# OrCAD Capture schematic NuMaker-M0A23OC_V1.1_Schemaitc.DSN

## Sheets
1 Nu-Link2-Me: size A3; title: Nu-Link2-Me; rev: 1.0; company: CMHuang; note: Nu-Link2-Me
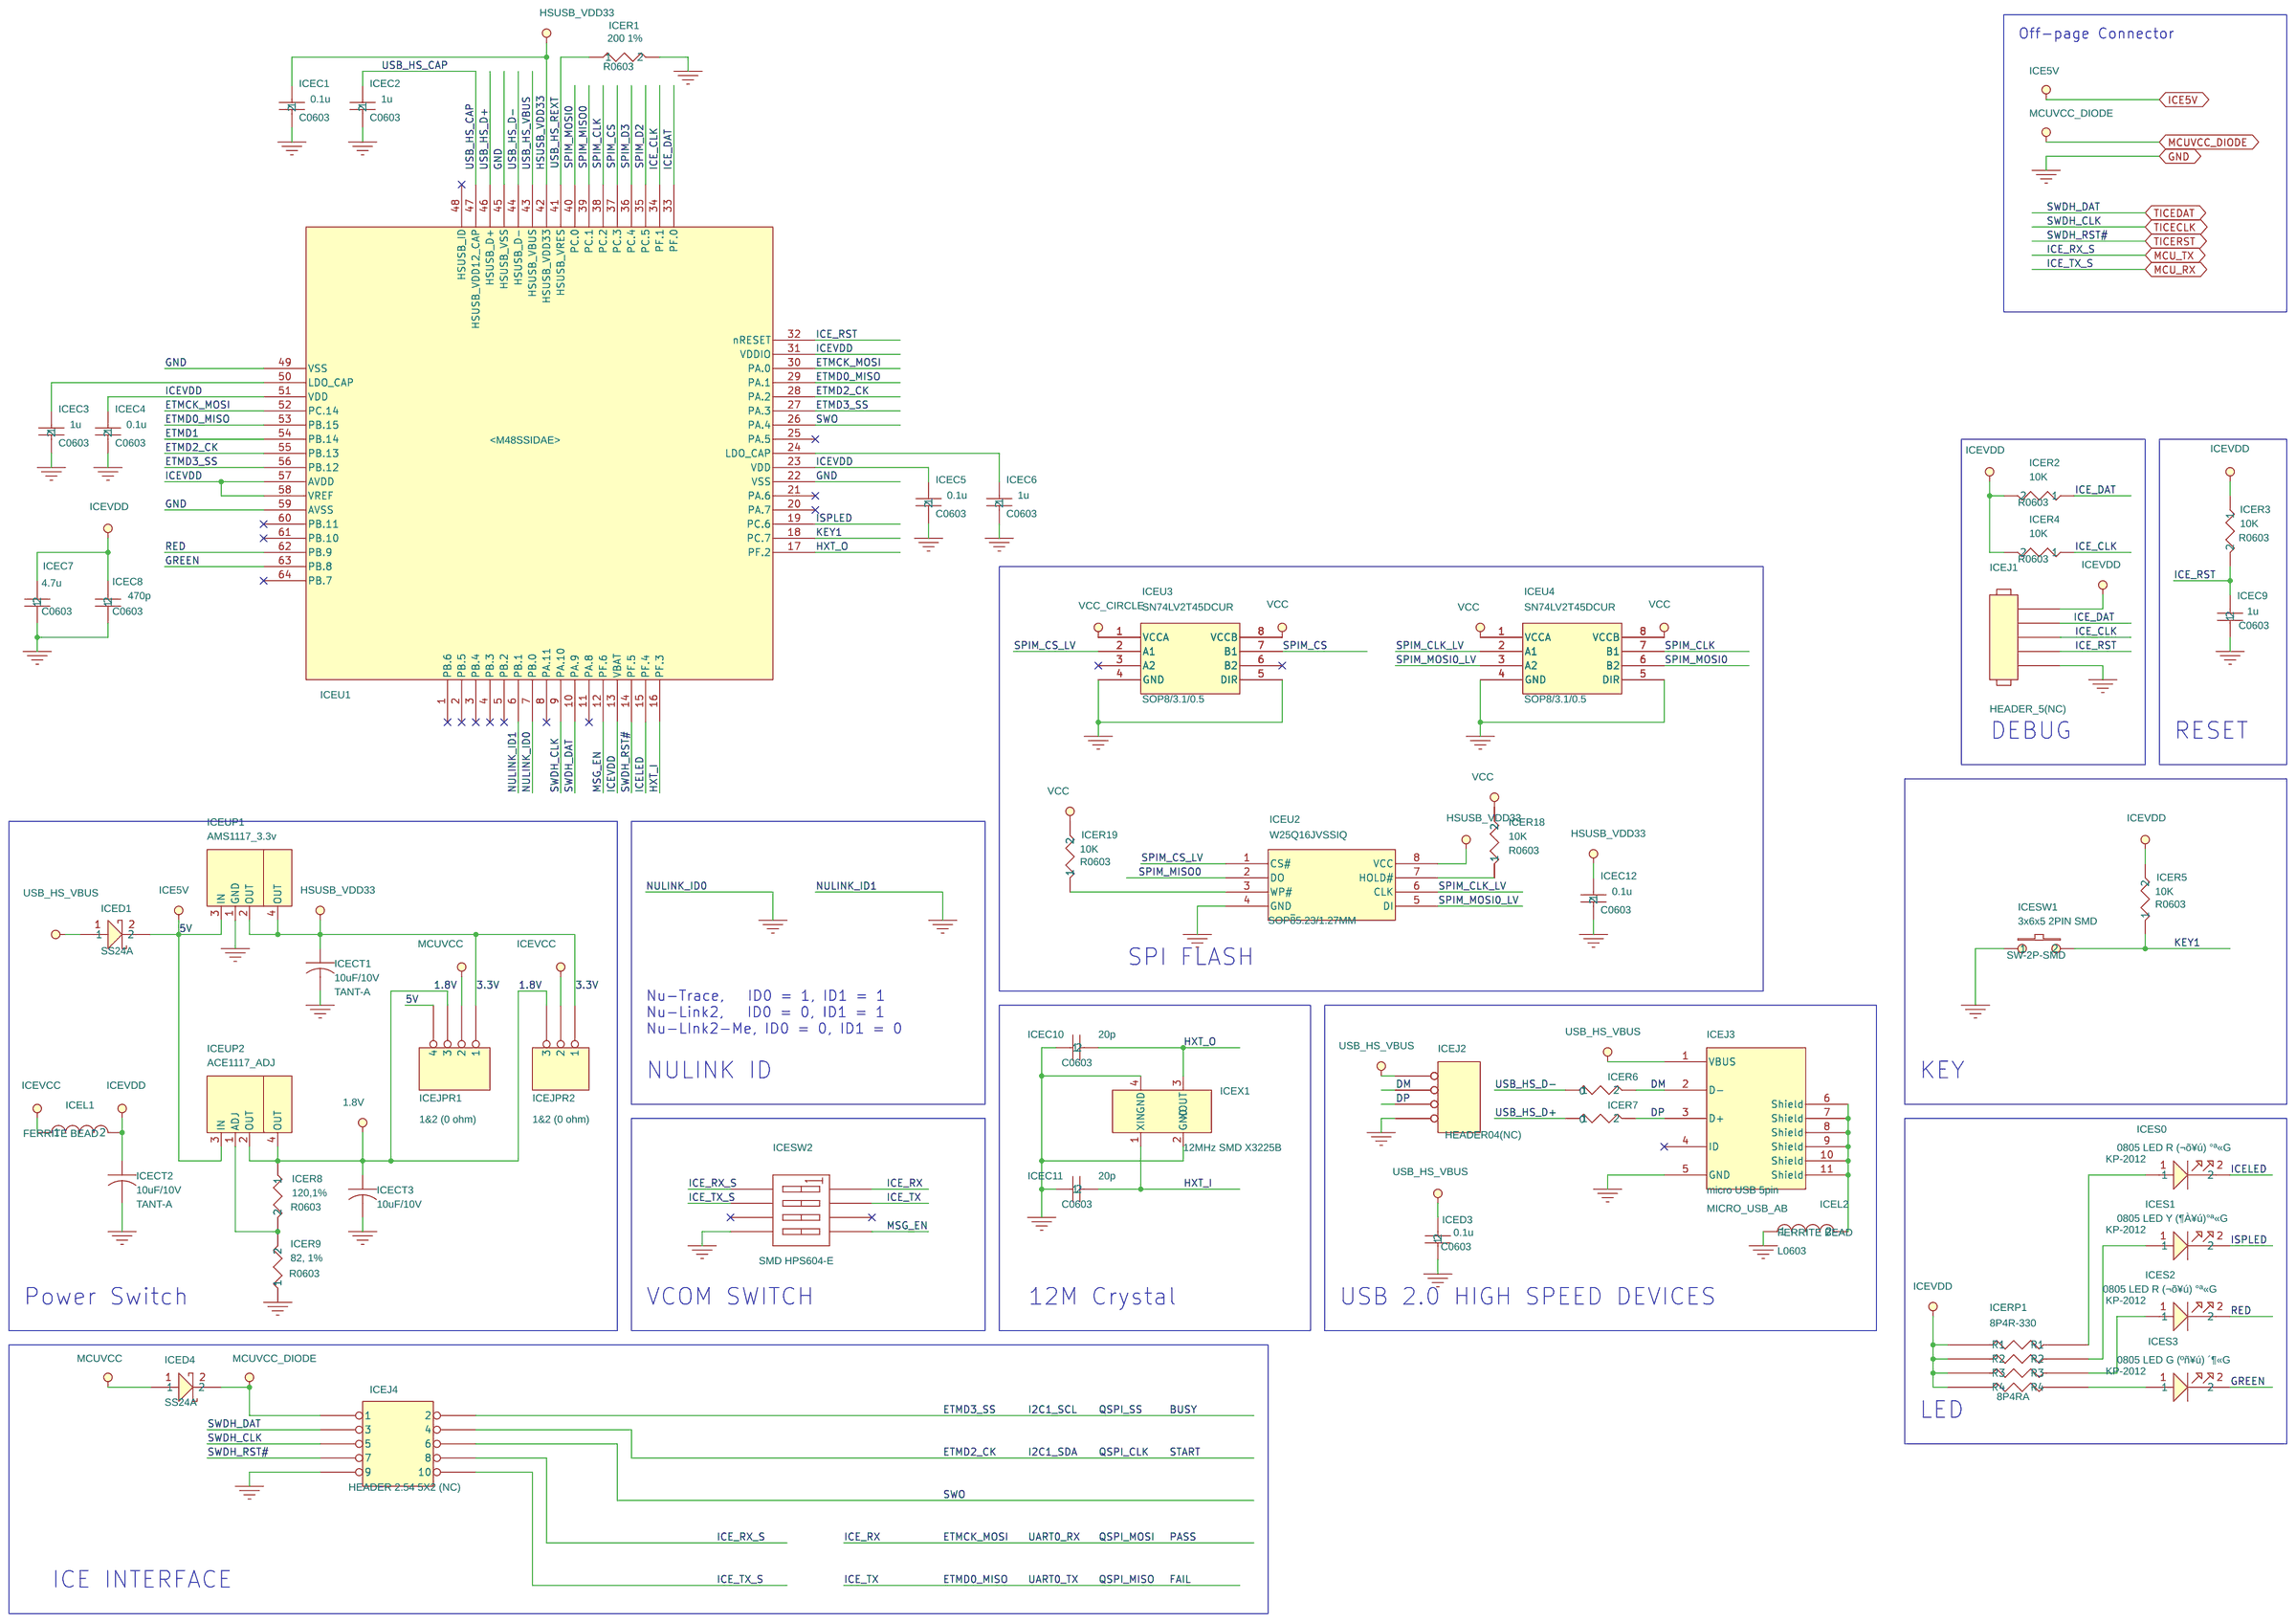
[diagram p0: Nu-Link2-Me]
2 M0A23OC1AC: size Custom; title: M0A23OC1AC; rev: v1.1; note: NuMaker-M0A23OC
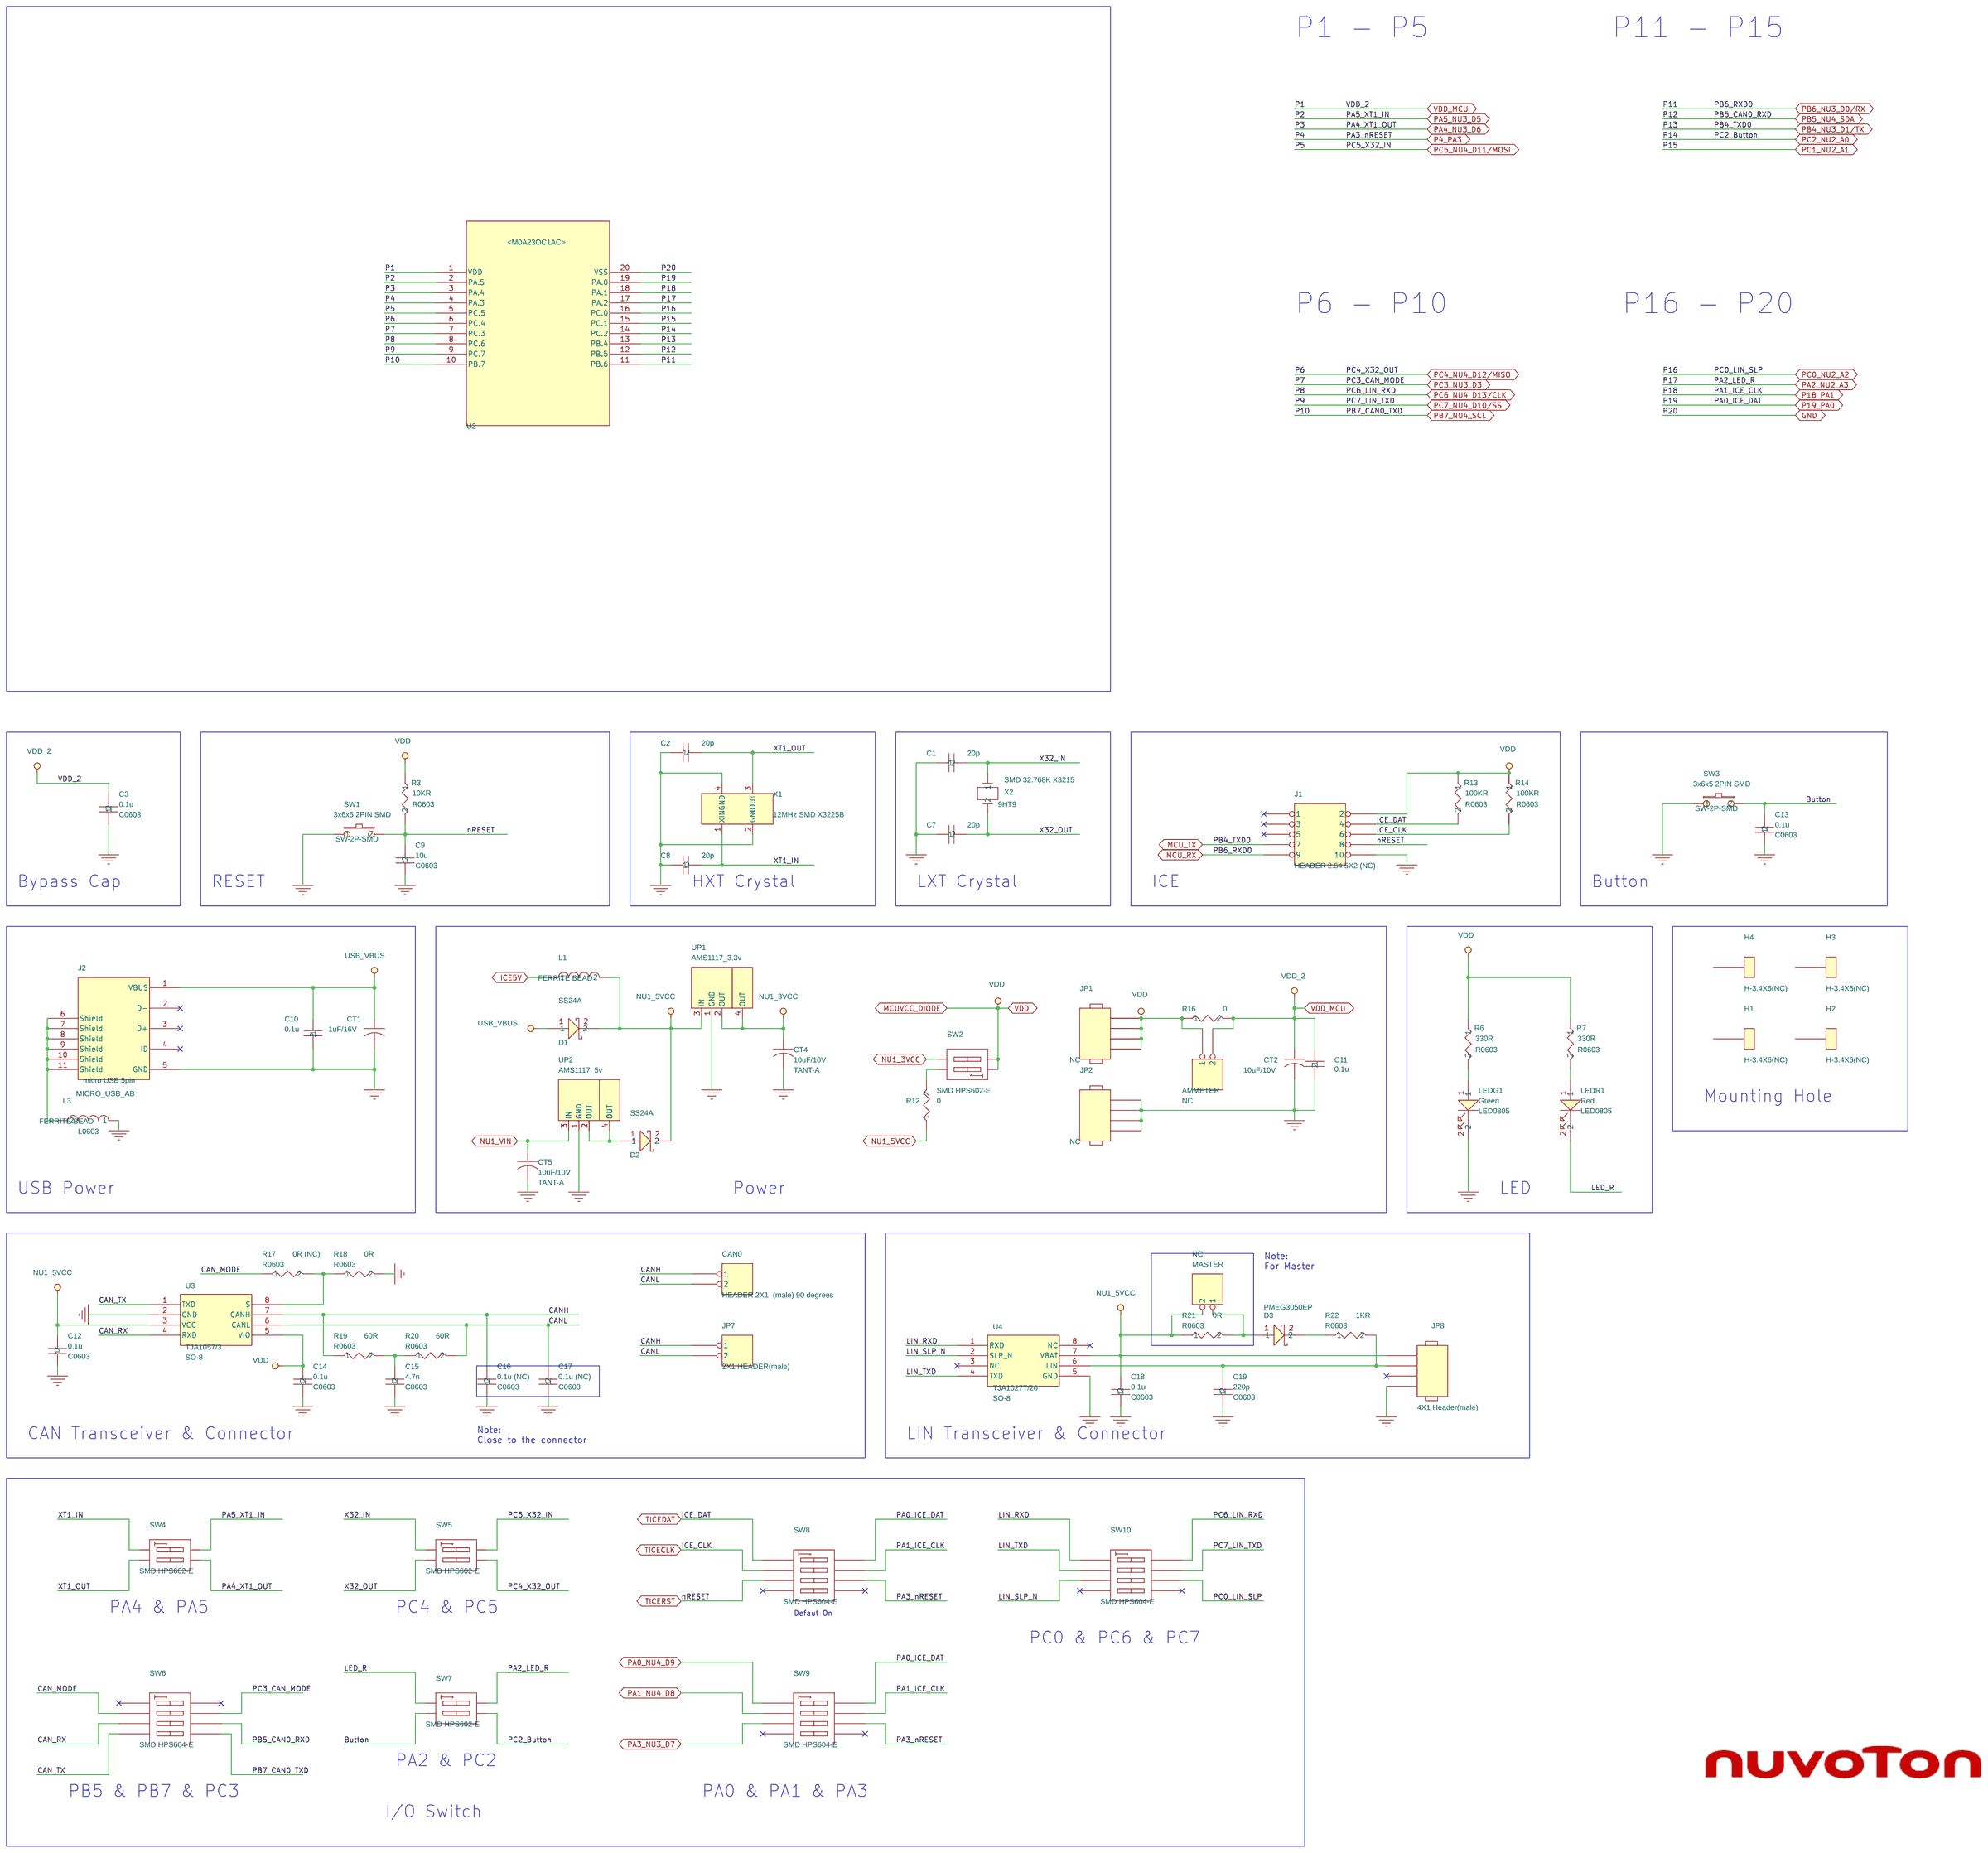
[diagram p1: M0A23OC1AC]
3 Ext. Connector: size Custom; title: Ext. Connector; rev: v1.1; note: NuMaker-M0A23OC
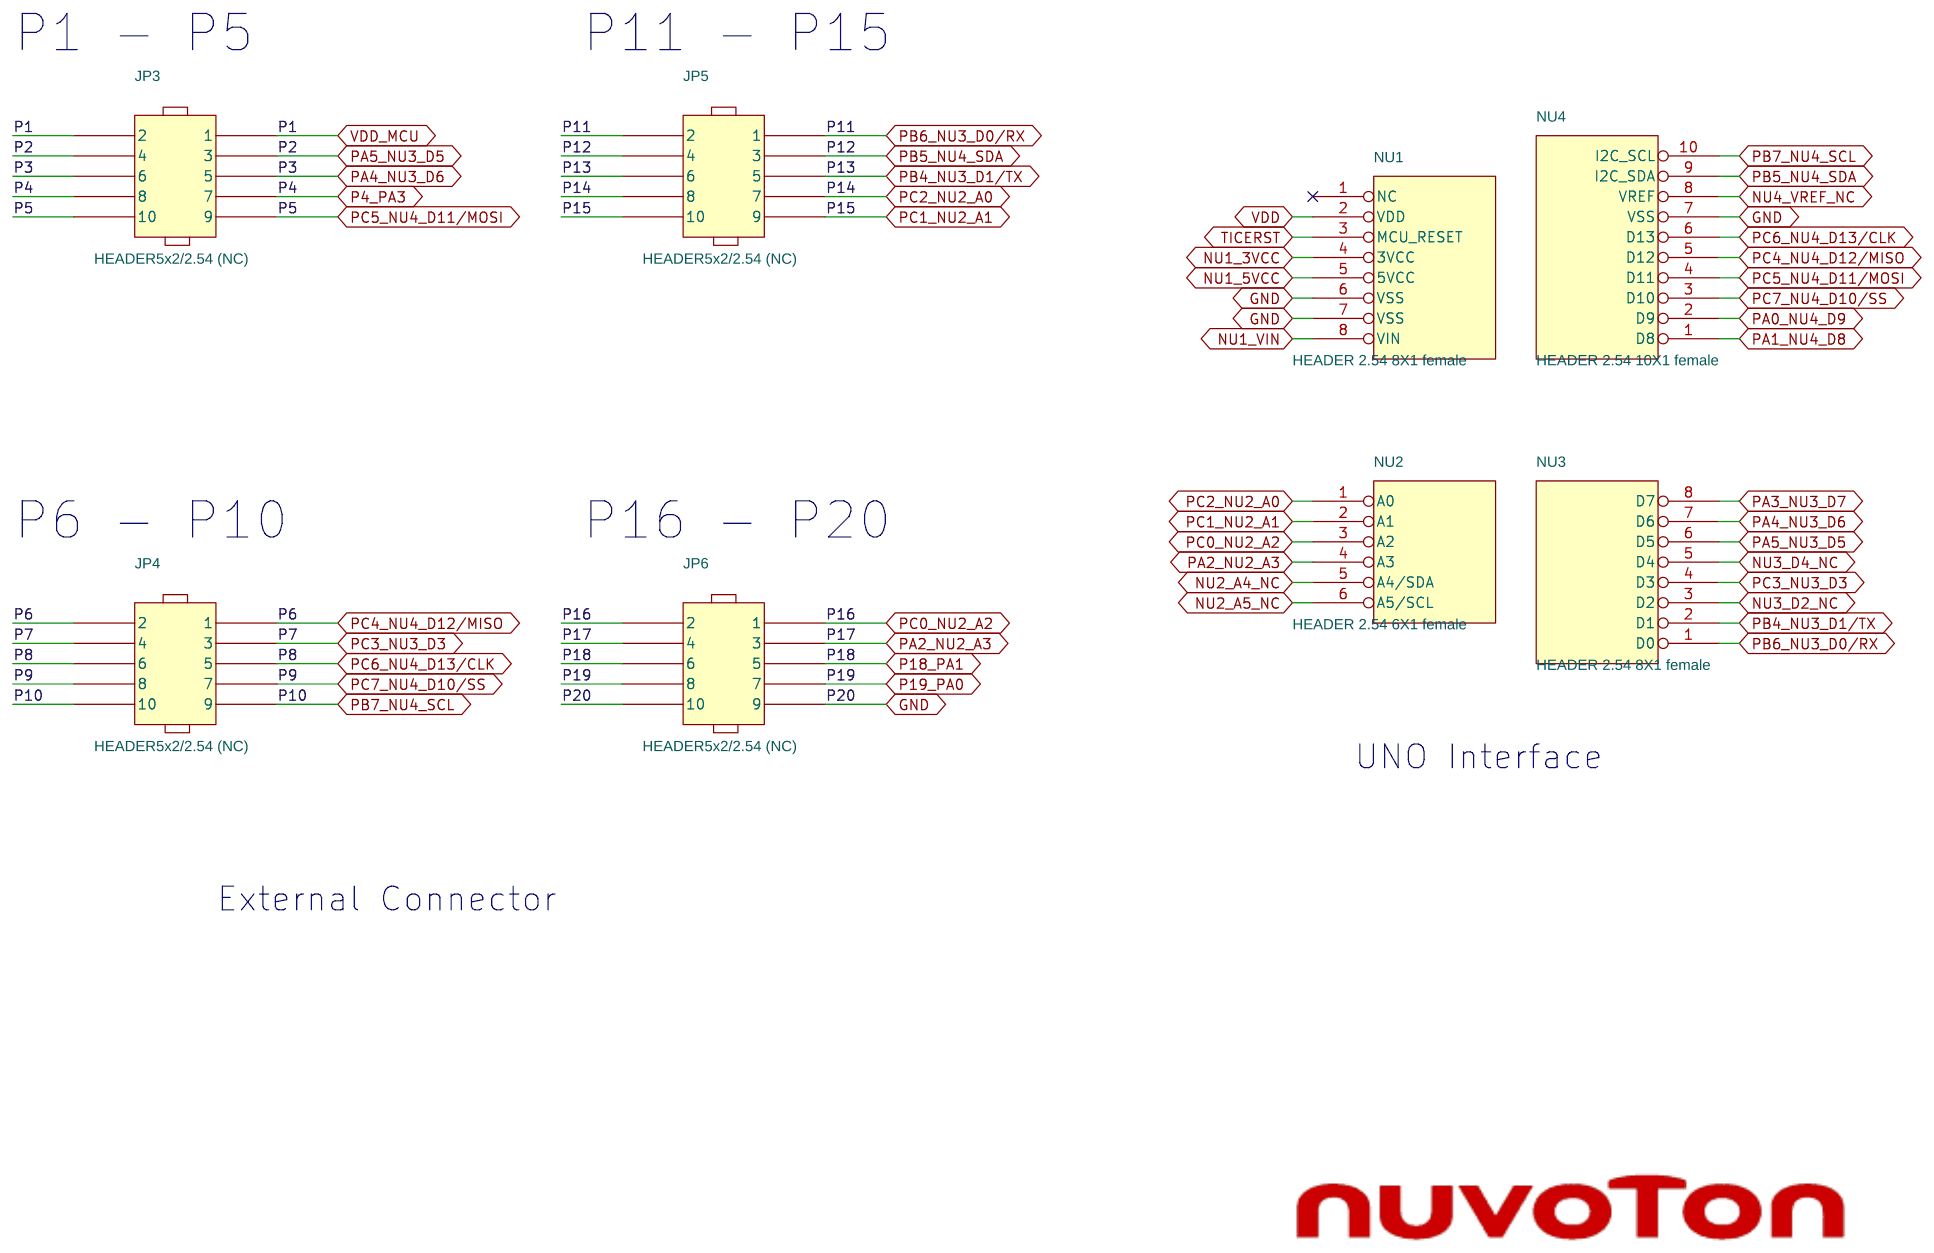
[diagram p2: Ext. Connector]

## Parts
sheet Ext. Connector
JP3  HEADER5x2/2.54 (NC)  [HEADER5x2/2.54]
JP4  HEADER5x2/2.54 (NC)  [HEADER5x2/2.54]
JP5  HEADER5x2/2.54 (NC)  [HEADER5x2/2.54]
JP6  HEADER5x2/2.54 (NC)  [HEADER5x2/2.54]
NU1  HEADER 2.54 8X1 female  [SIP-8P]
NU2  HEADER 2.54 6X1 female  [SIP-6P]
NU3  HEADER 2.54 8X1 female  [SIP-8P]
NU4  HEADER 2.54 10X1 female  [SIP-10P]
sheet M0A23OC1AC
AMMETER  NC  [HEADER2X1]
C1  20p  [C0603]
C2  20p  [C0603]
C3  0.1u  [C0603]
C7  20p  [C0603]
C8  20p  [C0603]
C9  10u  [C0603]
C10  0.1u  [C0603]
C11  0.1u  [C0603]
C12  0.1u  [C0603]
C13  0.1u  [C0603]
C14  0.1u  [C0603]
C15  4.7n  [C0603]
C16  0.1u (NC)  [C0603]
C17  0.1u (NC)  [C0603]
C18  0.1u  [C0603]
C19  220p  [C0603]
CAN0  HEADER 2X1  (male) 90 degrees  [SIP/2P_3.5MM]
CT1  1uF/16V  [TANT-A]
CT2  10uF/10V  [TANT-A]
CT4  10uF/10V  [TANT-A]
CT5  10uF/10V  [TANT-A]
D1  SS24A  [RB060L]
D2  SS24A  [RB060L]
D3  PMEG3050EP  [SOD-123-A(B)]
H1  H-3.4X6(NC)  [H-3.4X6]
H2  H-3.4X6(NC)  [H-3.4X6]
H3  H-3.4X6(NC)  [H-3.4X6]
H4  H-3.4X6(NC)  [H-3.4X6]
J1  HEADER 2.54 5X2 (NC)  [HEADER5X2]
J2  micro USB 5pin  [MICRO_USB_AB]
JP1  NC  [header1x4]
JP2  NC  [header1x4]
JP7  2X1 HEADER(male)  [HEADER2X1]
JP8  4X1 Header(male)  [header1x4]
L1  FERRITE BEAD  [L0603]
L3  FERRITE BEAD  [L0603]
LEDG1  Green  [LED0805]
LEDR1  Red  [LED0805]
MASTER  NC  [HEADER2X1]
R3  10KR  [R0603]
R6  330R  [R0603]
R7  330R  [R0603]
R12  0  [R0603]
R13  100KR  [R0603]
R14  100KR  [R0603]
R16  0  [R0603]
R17  0R (NC)  [R0603]
R18  0R  [R0603]
R19  60R  [R0603]
R20  60R  [R0603]
R21  0R  [R0603]
R22  1KR  [R0603]
SW1  3x6x5 2PIN SMD  [SW-2P-SMD]
SW2  SMD HPS602-E  [SW1X2]
SW3  3x6x5 2PIN SMD  [SW-2P-SMD]
SW4  SMD HPS602-E  [SW1X2]
SW5  SMD HPS602-E  [SW1X2]
SW6  SMD HPS604-E  [SW1X4]
SW7  SMD HPS602-E  [SW1X2]
SW8  SMD HPS604-E  [SW1X4]
SW9  SMD HPS604-E  [SW1X4]
SW10  SMD HPS604-E  [SW1X4]
U2  M0A23OC1AC  [MCU_SSOP20_7.8X7.2mm]
U3  TJA1057/3  [SO-8]
U4  TJA1027T/20  [SO-8]
UP1  AMS1117_3.3v  [SOT-223-1]
UP2  AMS1117_5v  [SOT-223-1]
X1  12MHz SMD X3225B  [CRYSTAL_SMD]
X2  SMD 32.768K X3215  [9HT9]
sheet Nu-Link2-Me
ICEC1  0.1u  [C0603]
ICEC2  1u  [C0603]
ICEC3  1u  [C0603]
ICEC4  0.1u  [C0603]
ICEC5  0.1u  [C0603]
ICEC6  1u  [C0603]
ICEC7  4.7u  [C0603]
ICEC8  470p  [C0603]
ICEC9  1u  [C0603]
ICEC10  20p  [C0603]
ICEC11  20p  [C0603]
ICEC12  0.1u  [C0603]
ICECT1  10uF/10V  [TANT-A]
ICECT2  10uF/10V  [TANT-A]
ICECT3  10uF/10V  [TANT-A]
ICED1  SS24A  [RB060L]
ICED3  0.1u  [C0603]
ICED4  SS24A  [RB060L]
ICEJ1  HEADER_5(NC)  [HEADER5X1]
ICEJ2  HEADER04(NC)  [HEADER04]
ICEJ3  micro USB 5pin  [MICRO_USB_AB]
ICEJ4  HEADER 2.54 5X2 (NC)  [HEADER5X2]
ICEJPR1  1&2 (0 ohm)  [R0603X3]
ICEJPR2  1&2 (0 ohm)  [R0603X2]
ICEL1  FERRITE BEAD  [L0603]
ICEL2  FERRITE BEAD  [L0603]
ICER1  200 1%  [R0603]
ICER2  10K  [R0603]
ICER3  10K  [R0603]
ICER4  10K  [R0603]
ICER5  10K  [R0603]
ICER6  0  [R0603]
ICER7  0  [R0603]
ICER8  120,1%  [R0603]
ICER9  82, 1%  [R0603]
ICER18  10K  [R0603]
ICER19  10K  [R0603]
ICERP1  8P4R-330  [8P4RA]
ICES0  0805 LED R (¬õ¥ú) °ª«G  [KP-2012]
ICES1  0805 LED Y (¶À¥ú)°ª«G  [KP-2012]
ICES2  0805 LED R (¬õ¥ú) °ª«G  [KP-2012]
ICES3  0805 LED G (ºñ¥ú) ´¶«G  [KP-2012]
ICESW1  3x6x5 2PIN SMD  [SW-2P-SMD]
ICESW2  SMD HPS604-E  [SW1X4]
ICEU1  M48SSIDAE  [LQFP64_7x7_M48SSIDAE]
ICEU2  W25Q16JVSSIQ  [SOP8\5.23/1.27MM]
ICEU3  SN74LV2T45DCUR  [SOP8/3.1/0.5]
ICEU4  SN74LV2T45DCUR  [SOP8/3.1/0.5]
ICEUP1  AMS1117_3.3v  [SOT-223-1]
ICEUP2  ACE1117_ADJ  [SOT-223-1]
ICEX1  12MHz SMD X3225B  [CRYSTAL_SMD]

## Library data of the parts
JP3 = HEADER_5X2
JP4 = HEADER_5X2_3
JP5 = HEADER_5X2_2
JP6 = HEADER_5X2_1
NU1 = POWER_CONNECT_0
NU2 = ADC_CONNECT_0
NU3 = PWM0_CONNECT_0
NU4 = PWM1_CONNECT_1
AMMETER = HEADER_2_1
C1 = C_20p_3
C2 = C_20p_1
C3 = CAP-C_6: Package: 0603; element_no: C0004
C7 = C_20p_2
C8 = C_20p
C9 = CAP-C_8: Package: 0603; element_no: C0006
C10 = C_0.1u_1: element_no: C0004
C11 = C_0.1u: element_no: C0004
C12 ICEC2 = CAP-C_9: Package: 0603; element_no: C0006
C13 ICEC3 = CAP-C_2: Package: 0603; element_no: C0006
C14 = CAP-C_3: Package: 0603; element_no: C0006
C15 = CAP-C_5: Package: 0603; element_no: C0006
C16 = CAP-C: Package: 0603; element_no: C0006
C17 ICEC9 = CAP-C_7: Package: 0603; element_no: C0006
C18 = CAP-C_4: Package: 0603; element_no: C0006
C19 = CAP-C_1: Package: 0603; element_no: C0006
CAN0 = HEADER_2_2
CT1 = C_1uF_16V
CT2 CT4 CT5 ICECT1-ICECT3 = C_10uF_10V
D1 = D_SS24A_2
D2 ICED1 = D_SS24A_1
D3 ICED4 = D_SS24A
H1-H4 = TEST_POINT
ICEJ4 J1 = HEADER_5X2_v2
ICEJ3 J2 = micro_USB_5pin_0
JP1 JP2 JP8 = HEADER_4_v2
JP7 = HEADER_2
ICEL1 L1 = FERRITE_BEAD
ICEL2 L3 = FERRITE_BEAD_1
LEDG1 = LED_0_1: Package: KP-2012; Vendor: Kingbright
LEDR1 = LED_0: Package: KP-2012; Vendor: Kingbright
MASTER = HEADER_2_0
ICER3 R3 = R_0_4: Package: 0603
R6 = R_0_9: Package: 0603
ICER2 R7 = R_0_1: Package: 0603
R12 = R_0_2
ICER5 R13 = R_0_8: Package: 0603
R14 = R_0_10: Package: 0603
R16 = R_0_12
R17 = R_0_11: Package: 0603
ICER19 R18 = R_0_7: Package: 0603
ICER1 R19 = R_0_5: Package: 0603
ICER18 R20 = R_0_6: Package: 0603
ICER8 R21 = R_0: Package: 0603
ICER4 R22 = R_0_3: Package: 0603
SW1 = SW_PUSHBUTTON_0_1
SW2 SW4 SW5 SW7 = SW_DIP-4_2
ICESW1 SW3 = SW_PUSHBUTTON_0
ICESW2 SW6 SW8-SW10 = SW_DIP-4_SM
U2 = M0A23OC1AC_0: M023XC1AC: <M0A23OC1AC>
U3 = TJA1057_3
U4 = TJA1027T_20
ICEUP1 UP1 UP2 = TO-247_Regulator_10
ICEX1 X1 = Crystal_SMD_1
X2 = Xtal_32.768K
ICEC1 = CAP-C_11: Package: 0603; element_no: C0004
ICEC4 = CAP-C_10: Package: 0603; element_no: C0004
ICEC5 = CAP-C: Package: 0603; element_no: C0004
ICEC6 = CAP-C_12: Package: 0603; element_no: C0006
ICEC7 = CAP-C_5: Package: 0603
ICEC8 = CAP-C_6: Package: 0603
ICEC10 = CAP-C_3: Package: 0603
ICEC11 = CAP-C_4: Package: 0603
ICEC12 = CAP-C_8: Package: 0603; element_no: C0004
ICED3 = CAP-C_1: Package: 0603; element_no: C0004
ICEJ1 = HEADER_5
ICEJ2 = HEADER_4
ICEJPR1 = HEADER_3_0
ICEJPR2 = HEADER_3
ICER6 = R_33
ICER7 = R_33_1
ICER9 = R_0_2: Package: 0603
ICERP1 = R-PACK8_0
ICES0 = LED_0_3: Vendor: Kingbright
ICES1 = LED_0_2: Vendor: Kingbright
ICES2 = LED_0_1: Vendor: Kingbright
ICES3 = LED_0: Vendor: Kingbright
ICEU1 = M487SIDAE_0: M487SIDAE: <M48SSIDAE>
ICEU2 = W25P10_20_40_SOIC_0: Package: SOP8; Vendor: WINBOND
ICEU3 ICEU4 = SN74LV2T45
ICEUP2 = TO-247_Regulator_0

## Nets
1.8V: ICECT3.1 ICEJPR1.3 ICEJPR2.3 ICER8.1 ICEUP2.2(OUT) ICEUP2.4(OUT)
3.3V: ICEC1.1 ICEC12.1 ICECT1.1 ICEJPR1.1 ICEJPR2.1 ICER18.2 ICER19.2 ICEU1.42(HSUSB_VDD33) ICEU2.8(VCC) ICEU3.1(VCCA) ICEU4.1(VCCA) ICEUP1.2(OUT) ICEUP1.4(OUT)
GND: C1.1 C2.1 C3.1 C7.1 C8.1 C9.1 C10.2 C11.2 C12.1 C13.1 C14.1 C15.1 C16.1 C17.1 C18.1 C19.1 CT1.2 CT2.2 CT4.2 CT5.2 ICEC1.2 ICEC2.2 ICEC3.2 ICEC4.2 ICEC5.2 ICEC6.2 ICEC7.1 ICEC8.1 ICEC9.1 ICEC10.1 ICEC11.1 ICEC12.2 ICECT1.2 ICECT2.2 ICECT3.2 ICED3.1 ICEJ1.5 ICEJ2.4 ICEJ3.5(GND) ICEJ4.9 ICEL2.1 ICER1.2 ICER9.1 ICESW1.1 ICESW2.4(A4) ICEU1.6(PB.1) ICEU1.7(PB.0) ICEU1.22(VSS) ICEU1.45(HSUSB_VSS) ICEU1.49(VSS) ICEU1.59(AVSS) ICEU2.4(GND) ICEU3.4(GND) ICEU3.5(DIR) ICEU4.4(GND) ICEU4.5(DIR) ICEUP1.1(GND) ICEX1.2(GND) ICEX1.4(GND) J1.10 J2.5(GND) JP2.1 JP2.2 JP2.3 JP2.4 JP6.9 JP6.10 JP8.4 L3.1 LEDG1.2 NU1.6(VSS) NU1.7(VSS) NU4.7(VSS) R18.2 SW1.1 SW3.1 U2.20(VSS) U3.2(GND) U4.5(GND) UP1.1(GND) UP2.1(GND) X1.2(GND) X1.4(GND)
VDD: AMMETER.1 C14.2 ICED4.2 ICEJ4.1 J1.2 JP1.1 JP1.2 JP1.3 JP1.4 NU1.2(VDD) R3.1 R6.1 R7.1 R13.1 R14.1 R16.1 SW2.3(B1) SW2.4(B2) U3.5(VIO)
VDD_MCU: AMMETER.2 C3.2 C11.1 CT2.1 JP3.1 JP3.2 R16.2 U2.1(VDD)
BUSY: ICEJ4.2 ICEU1.27(PA.3) ICEU1.56(PB.12)
Button: C13.2 SW3.2 SW7.3(B1)
CAN_MODE: R17.1 SW6.7(B2)
CAN_RX: SW6.6(B3) U3.4(RXD)
CAN_TX: SW6.5(B4) U3.1(TXD)
CANH: C16.2 CAN0.1 JP7.1 R19.1 U3.7(CANH)
CANL: C17.2 CAN0.2 JP7.2 R20.2 U3.6(CANL)
DM: ICEJ2.2 ICEJ3.2(D-) ICER6.2
DP: ICEJ2.3 ICEJ3.3(D+) ICER7.2
ETMD1: ICEU1.54(PB.14)
ETMD2_CK: ICEJ4.4 ICEU1.28(PA.2) ICEU1.55(PB.13)
GREEN: ICES3.2 ICEU1.63(PB.8)
HXT_I: ICEC11.2 ICEU1.16(PF.3) ICEX1.1(XIN)
HXT_O: ICEC10.2 ICEU1.17(PF.2) ICEX1.3(XOUT)
ICE5V: ICED1.2 ICEJPR1.4 ICEUP1.3(IN) ICEUP2.3(IN) L1.1
ICE_CLK: ICEJ1.3 ICER4.1 ICEU1.34(PF.1)
ICE_DAT: ICEJ1.2 ICER2.1 ICEU1.33(PF.0)
ICE_RST: ICEC9.2 ICEJ1.4 ICER3.2 ICEU1.32(nRESET)
ICE_RX: ICESW2.8(B1) ICEU1.30(PA.0) ICEU1.52(PC.14)
ICE_TX: ICESW2.7(B2) ICEU1.29(PA.1) ICEU1.53(PB.15)
ICELED: ICES0.2 ICEU1.15(PF.4)
ICEVCC: ICEJPR2.2 ICEL1.1
ICEVDD: ICEC4.1 ICEC5.1 ICEC7.2 ICEC8.2 ICECT2.1 ICEJ1.1 ICEL1.2 ICER2.2 ICER3.1 ICER4.2 ICER5.2 ICERP1.1(R1) ICERP1.3(R2) ICERP1.5(R3) ICERP1.7(R4) ICEU1.13(VBAT) ICEU1.23(VDD) ICEU1.31(VDDIO) ICEU1.51(VDD) ICEU1.57(AVDD) ICEU1.58(VREF) ICEU3.8(VCCB) ICEU4.8(VCCB)
ISPLED: ICES1.2 ICEU1.19(PC.6)
KEY1: ICER5.1 ICESW1.2 ICEU1.18(PC.7)
LED_R: LEDR1.2 SW7.4(B2)
LIN_RXD: SW10.8(B1) U4.1(RXD)
LIN_SLP_N: SW10.6(B3) U4.2(SLP_N)
LIN_TXD: SW10.7(B2) U4.4(TXD)
MCU_RX: ICEJ4.10 ICESW2.2(A2) J1.9 JP5.1 JP5.2 NU3.1(D0) U2.11(PB.6)
MCU_TX: ICEJ4.8 ICESW2.1(A1) J1.7 JP5.5 JP5.6 NU3.2(D1) U2.13(PB.4)
MCUVCC: ICED4.1 ICEJPR1.2
MSG_EN: ICESW2.5(B4) ICEU1.12(PF.6)
NU1_3VCC: CT4.1 NU1.4(3VCC) SW2.2(A2) UP1.2(OUT) UP1.4(OUT)
NU1_5VCC: C12.2 C18.2 D1.2 D2.2 JP8.1 L1.2 MASTER.2 NU1.5(5VCC) R12.1 R21.1 U3.3(VCC) U4.7(VBAT) UP1.3(IN)
NU1_VIN: CT5.1 NU1.8(VIN) UP2.3(IN)
NU2_A4_NC: NU2.5(A4/SDA)
NU2_A5_NC: NU2.6(A5/SCL)
NU3_D2_NC: NU3.3(D2)
NU3_D4_NC: NU3.5(D4)
NU4_VREF_NC: NU4.8(VREF)
P4_PA3: JP3.7 JP3.8 SW8.3(A3) SW9.3(A3) U2.4(PA.3)
P18_PA1: JP6.5 JP6.6 SW8.2(A2) SW9.2(A2) U2.18(PA.1)
P19_PA0: JP6.7 JP6.8 SW8.1(A1) SW9.1(A1) U2.19(PA.0)
PA0_NU4_D9: NU4.2(D9) SW9.8(B1)
PA1_NU4_D8: NU4.1(D8) SW9.7(B2)
PA2_NU2_A3: JP6.3 JP6.4 NU2.4(A3) SW7.1(A1) U2.17(PA.2)
PA3_NU3_D7: NU3.8(D7) SW9.6(B3)
PA4_NU3_D6: JP3.5 JP3.6 NU3.7(D6) SW4.2(A2) U2.3(PA.4)
PA5_NU3_D5: JP3.3 JP3.4 NU3.6(D5) SW4.1(A1) U2.2(PA.5)
PB5_NU4_SDA: JP5.3 JP5.4 NU4.9(I2C_SDA) SW6.3(A3) U2.12(PB.5)
PB7_NU4_SCL: JP4.9 JP4.10 NU4.10(I2C_SCL) SW6.4(A4) U2.10(PB.7)
PC0_NU2_A2: JP6.1 JP6.2 NU2.3(A2) SW10.3(A3) U2.16(PC.0)
PC1_NU2_A1: JP5.9 JP5.10 NU2.2(A1) U2.15(PC.1)
PC2_NU2_A0: JP5.7 JP5.8 NU2.1(A0) SW7.2(A2) U2.14(PC.2)
PC3_NU3_D3: JP4.3 JP4.4 NU3.4(D3) SW6.2(A2) U2.7(PC.3)
PC4_NU4_D12/MISO: JP4.1 JP4.2 NU4.5(D12) SW5.2(A2) U2.6(PC.4)
PC5_NU4_D11/MOSI: JP3.9 JP3.10 NU4.4(D11) SW5.1(A1) U2.5(PC.5)
PC6_NU4_D13/CLK: JP4.5 JP4.6 NU4.6(D13) SW10.1(A1) U2.8(PC.6)
PC7_NU4_D10/SS: JP4.7 JP4.8 NU4.3(D10) SW10.2(A2) U2.9(PC.7)
RED: ICES2.2 ICEU1.62(PB.9)
SPIM_CLK: ICEU1.38(PC.2) ICEU4.7(B1)
SPIM_CLK_LV: ICEU2.6(CLK) ICEU4.2(A1)
SPIM_CS: ICEU1.37(PC.3) ICEU3.7(B1)
SPIM_CS_LV: ICEU2.1(CS#) ICEU3.2(A1)
SPIM_D2: ICEU1.35(PC.5)
SPIM_D3: ICEU1.36(PC.4)
SPIM_MISO0: ICEU1.39(PC.1) ICEU2.2(DO)
SPIM_MOSI0: ICEU1.40(PC.0) ICEU4.6(B2)
SPIM_MOSI0_LV: ICEU2.5(DI) ICEU4.3(A2)
SWO: ICEJ4.6 ICEU1.26(PA.4)
TICECLK: ICEJ4.5 ICEU1.9(PA.10) J1.6 R14.2 SW8.7(B2)
TICEDAT: ICEJ4.3 ICEU1.10(PA.9) J1.4 R13.2 SW8.8(B1)
TICERST: C9.2 ICEJ4.7 ICEU1.14(PF.5) J1.8 NU1.3(MCU_RESET) R3.2 SW1.2 SW8.6(B3)
USB_HS_CAP: ICEC2.1 ICEU1.47(HSUSB_VDD12_CAP)
USB_HS_D+: ICER7.1 ICEU1.46(HSUSB_D+)
USB_HS_D-: ICER6.1 ICEU1.44(HSUSB_D-)
USB_HS_REXT: ICER1.1 ICEU1.41(HSUSB_VRES)
USB_HS_VBUS: ICED1.1 ICED3.2 ICEJ2.1 ICEJ3.1(VBUS) ICEU1.43(HSUSB_VBUS)
USB_VBUS: C10.1 CT1.1 D1.1 J2.1(VBUS)
X32_IN: C1.2 SW5.4(B2) X2.1
X32_OUT: C7.2 SW5.3(B1) X2.2
XT1_IN: C8.2 SW4.4(B2) X1.1(XIN)
XT1_OUT: C2.2 SW4.3(B1) X1.3(XOUT)
N16825237: LEDG1.1 R6.2
N16825240: LEDR1.1 R7.2
N16840819: ICEC6.1 ICEU1.24(LDO_CAP)
N16840960: ICEC3.1 ICEU1.50(LDO_CAP)
N17019924: ICER8.2 ICER9.2 ICEUP2.1(ADJ)
N17029977: ICERP1.8(R4) ICES3.1
N17029979: ICERP1.6(R3) ICES2.1
N17030004: ICERP1.4(R2) ICES1.1
N17030010: ICERP1.2(R1) ICES0.1
N17042369: ICEJ3.6(Shield) ICEJ3.7(Shield) ICEJ3.8(Shield) ICEJ3.9(Shield) ICEJ3.10(Shield) ICEJ3.11(Shield) ICEL2.2
N17110356: J2.6(Shield) J2.7(Shield) J2.8(Shield) J2.9(Shield) J2.10(Shield) J2.11(Shield) L3.2
N17155328: ICER18.1 ICEU2.7(HOLD#)
N17155343: ICER19.1 ICEU2.3(WP#)
N17167442: D2.1 UP2.2(OUT) UP2.4(OUT)
N17232049: R12.2 SW2.1(A1)
N17236067: C15.2 R19.2 R20.1
N17236115: R17.2 R18.1 U3.8(S)
N17291463: C19.2 JP8.2 R22.2 U4.6(LIN)
N17291566: D3.2 R22.1
N17291605: D3.1 MASTER.1 R21.2

Not connected (* = marked no-connect by the designer): H1 1; H2 1; H3 1; H4 1; ICEJ3 4(ID)*; ICESW2 3(A3)* 6(B3)*; ICEU1 1(PB.6)* 2(PB.5)* 3(PB.4)* 4(PB.3)* 5(PB.2)* 8(PA.11)* 11(PA.8)* 20(PA.7)* 21(PA.6)* 25(PA.5)* 48(HSUSB_ID)* 60(PB.11)* 61(PB.10)* 64(PB.7)*; ICEU3 3(A2)* 6(B2)*; J1 1* 3* 5*; J2 2(D-)* 3(D+)* 4(ID)*; JP8 3*; NU1 1(NC)*; SW6 1(A1)* 8(B1)*; SW8 4(A4)* 5(B4)*; SW9 4(A4)* 5(B4)*; SW10 4(A4)* 5(B4)*; U4 3(NC)* 8(NC)*

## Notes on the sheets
sheet 1
- Off-page Connector
- DEBUG
- RESET
- SPI FLASH
- Nu-Trace,   ID0 = 1, ID1 = 1
  Nu-Link2,   ID0 = 0, ID1 = 1
  Nu-LInk2-Me, ID0 = 0, ID1 = 0
- NULINK ID
- KEY
- Power Switch
- VCOM SWITCH
- 12M Crystal
- USB 2.0 HIGH SPEED DEVICES
- LED
- ICE INTERFACE
sheet 2
- P1 - P5
- P11 - P15
- P6 - P10
- P16 - P20
- Bypass Cap
- RESET
- HXT Crystal
- LXT Crystal
- ICE
- Button
- Mounting Hole
- USB Power
- Power
- LED
- Note:
  For Master
- CAN Transceiver & Connector
- Note:
  Close to the connector
- LIN Transceiver & Connector
- PA4 & PA5
- PC4 & PC5
- Defaut On
- PC0 & PC6 & PC7
- PA2 & PC2
- PB5 & PB7 & PC3
- PA0 & PA1 & PA3
- I/O Switch
sheet 3
- P1 - P5
- P11 - P15
- P6 - P10
- P16 - P20
- UNO Interface
- External Connector
